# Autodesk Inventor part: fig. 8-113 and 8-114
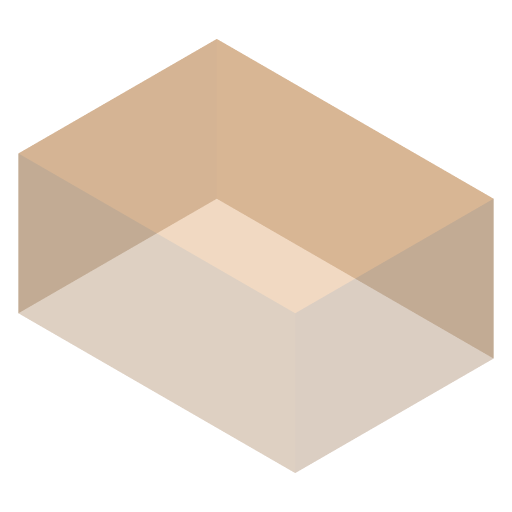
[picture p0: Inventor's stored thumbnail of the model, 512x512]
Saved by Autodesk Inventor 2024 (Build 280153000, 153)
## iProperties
Created: 2013-07
Part Number: fig. 8-113 and 8-114
Material: Generic
Document SubType Name: Modeling
Designer: CADCIM
Density: 1 g/cm^3
Appearance: Default
Author: CADCIM
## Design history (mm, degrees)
sketch "Sketch1"
  geometry: L1 (-10, 7.167)-(10, 7.167); L2 (10, 7.167)-(10, -7.167); L3 (10, -7.167)-(-10, -7.167); L4 (-10, -7.167)-(-10, 7.167); L5 (-10, 7.167)-(10, -7.167); L6 (10, 7.167)-(-10, -7.167); 1 further point
  constraints: 12 end point, 2 equal length, 2 midpoint, 1 horizontal, 1 parallel
  dimensions: "d0" = 20 distance of L2.end L3.end
extrude_surface "ExtrusionSrf1" sketch "Sketch1" dims "d1" = 10, "d2" = 0
patch "Boundary Patch1" dims "d3" = 5, "d4" = 0
body "Srf1"
body "Srf2"
